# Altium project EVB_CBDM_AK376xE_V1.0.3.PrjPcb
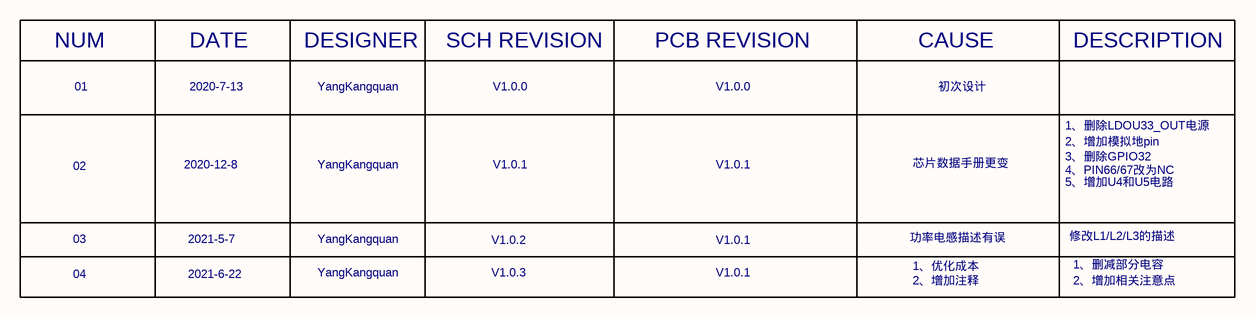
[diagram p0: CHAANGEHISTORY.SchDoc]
7 sheets, 156 parts. Net scope: flat (ports and power ports of the same name join across sheets).
Sheets:
  CHAANGEHISTORY.SchDoc
  BLOCK_DIAGRAM.SchDoc
  INTERFACE_CORE.SchDoc
  AK376xE_POWER.SchDoc
  AK376xE_FLASH.SchDoc
  AK376xE_MIC.SchDoc
  POWER.SchDoc

## Sheet CHAANGEHISTORY.SchDoc: EVB_CBDM_AK376xE_V1.0.3
size A4; Revision: V1.0.3; SheetNumber: 1; SheetTotal: 7

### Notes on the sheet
- NUM
- 01
- DATE
- 2020-7-13
- DESIGNER
- YangKangquan
- SCH REVISION
- V1.0.0
- PCB REVISION
- CAUSE
- 初次设计
- DESCRIPTION
- 02
- 2020-12-8
- V1.0.1
- 芯片数据手册更变
- 1、删除LDOU33_OUT电源
- 2、增加模拟地pin
- 3、删除GPIO32
- 4、PIN66/67改为NC
- 03
- 2021-5-7
- V1.0.2
- 功率电感描述有误
- 5、增加U4和U5电路
- 修改L1/L2/L3的描述
- 04
- 2021-6-22
- V1.0.3
- 1、优化成本
- 2、增加注释
- 1、删减部分电容
- 2、增加相关注意点

## Sheet BLOCK_DIAGRAM.SchDoc: EVB_CBDM_AK376xE_V1.0.3
size A4; Revision: V1.0.3; SheetNumber: 2; SheetTotal: 7
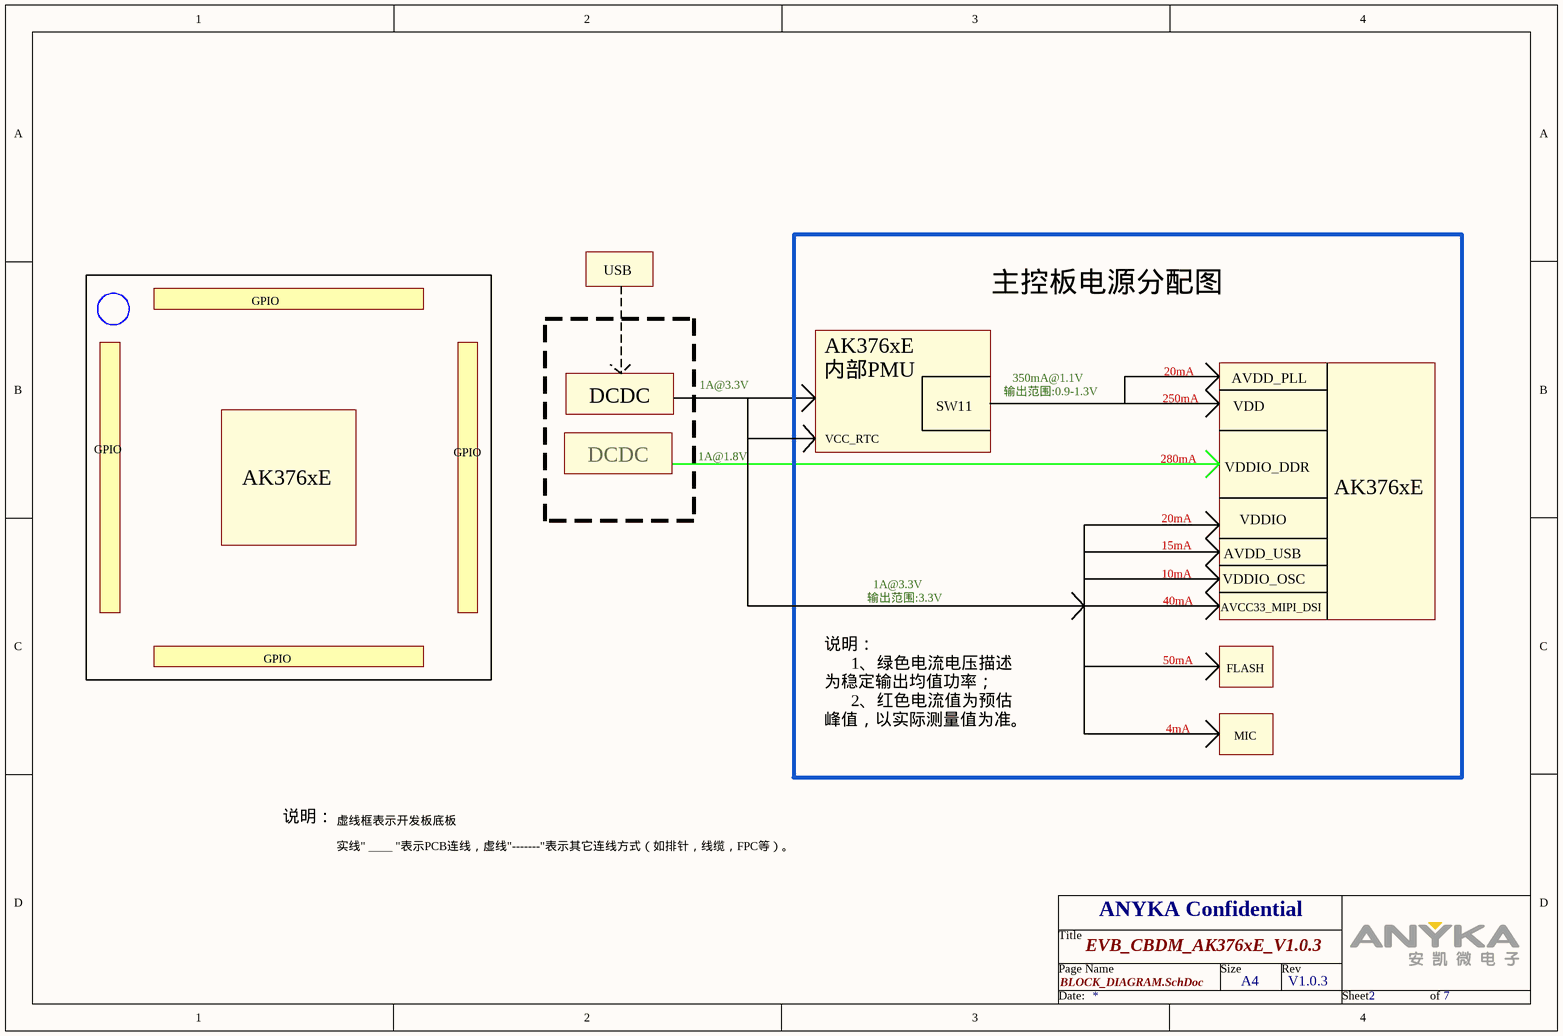
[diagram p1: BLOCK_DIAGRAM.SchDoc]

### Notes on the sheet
- GPIO
- USB
- 主控板电源分配图
- AK376xE
  内部PMU
- 20mA
- AVDD_PLL
- DCDC
- 1A@3.3V
- VCC_RTC
- 350mA@1.1V
  输出范围:0.9-1.3V
- 250mA
- VDD
- AK376xE
- 1A@1.8V
- SW11
- 280mA
- VDDIO_DDR
- 10mA
- 15mA
- AVDD_USB
- VDDIO_OSC
- VDDIO
- 1A@3.3V
  输出范围:3.3V
- 40mA
- AVCC33_MIPI_DSI
- 50mA
- FLASH
- 说明：
  1、绿色电流电压描述为稳定输出均值功率；
  2、红色电流值为预估峰值，以实际测量值为准。
- 4mA
- MIC
- 说明：
- 虚线框表示开发板底板
- 实线" ____ "表示PCB连线，虚线"-------"表示其它连线方式（如排针，线缆，FPC等）。

## Sheet INTERFACE_CORE.SchDoc: EVB_CBDM_AK376xE_V1.0.3
size A4; Revision: V1.0.3; SheetNumber: 3; SheetTotal: 7
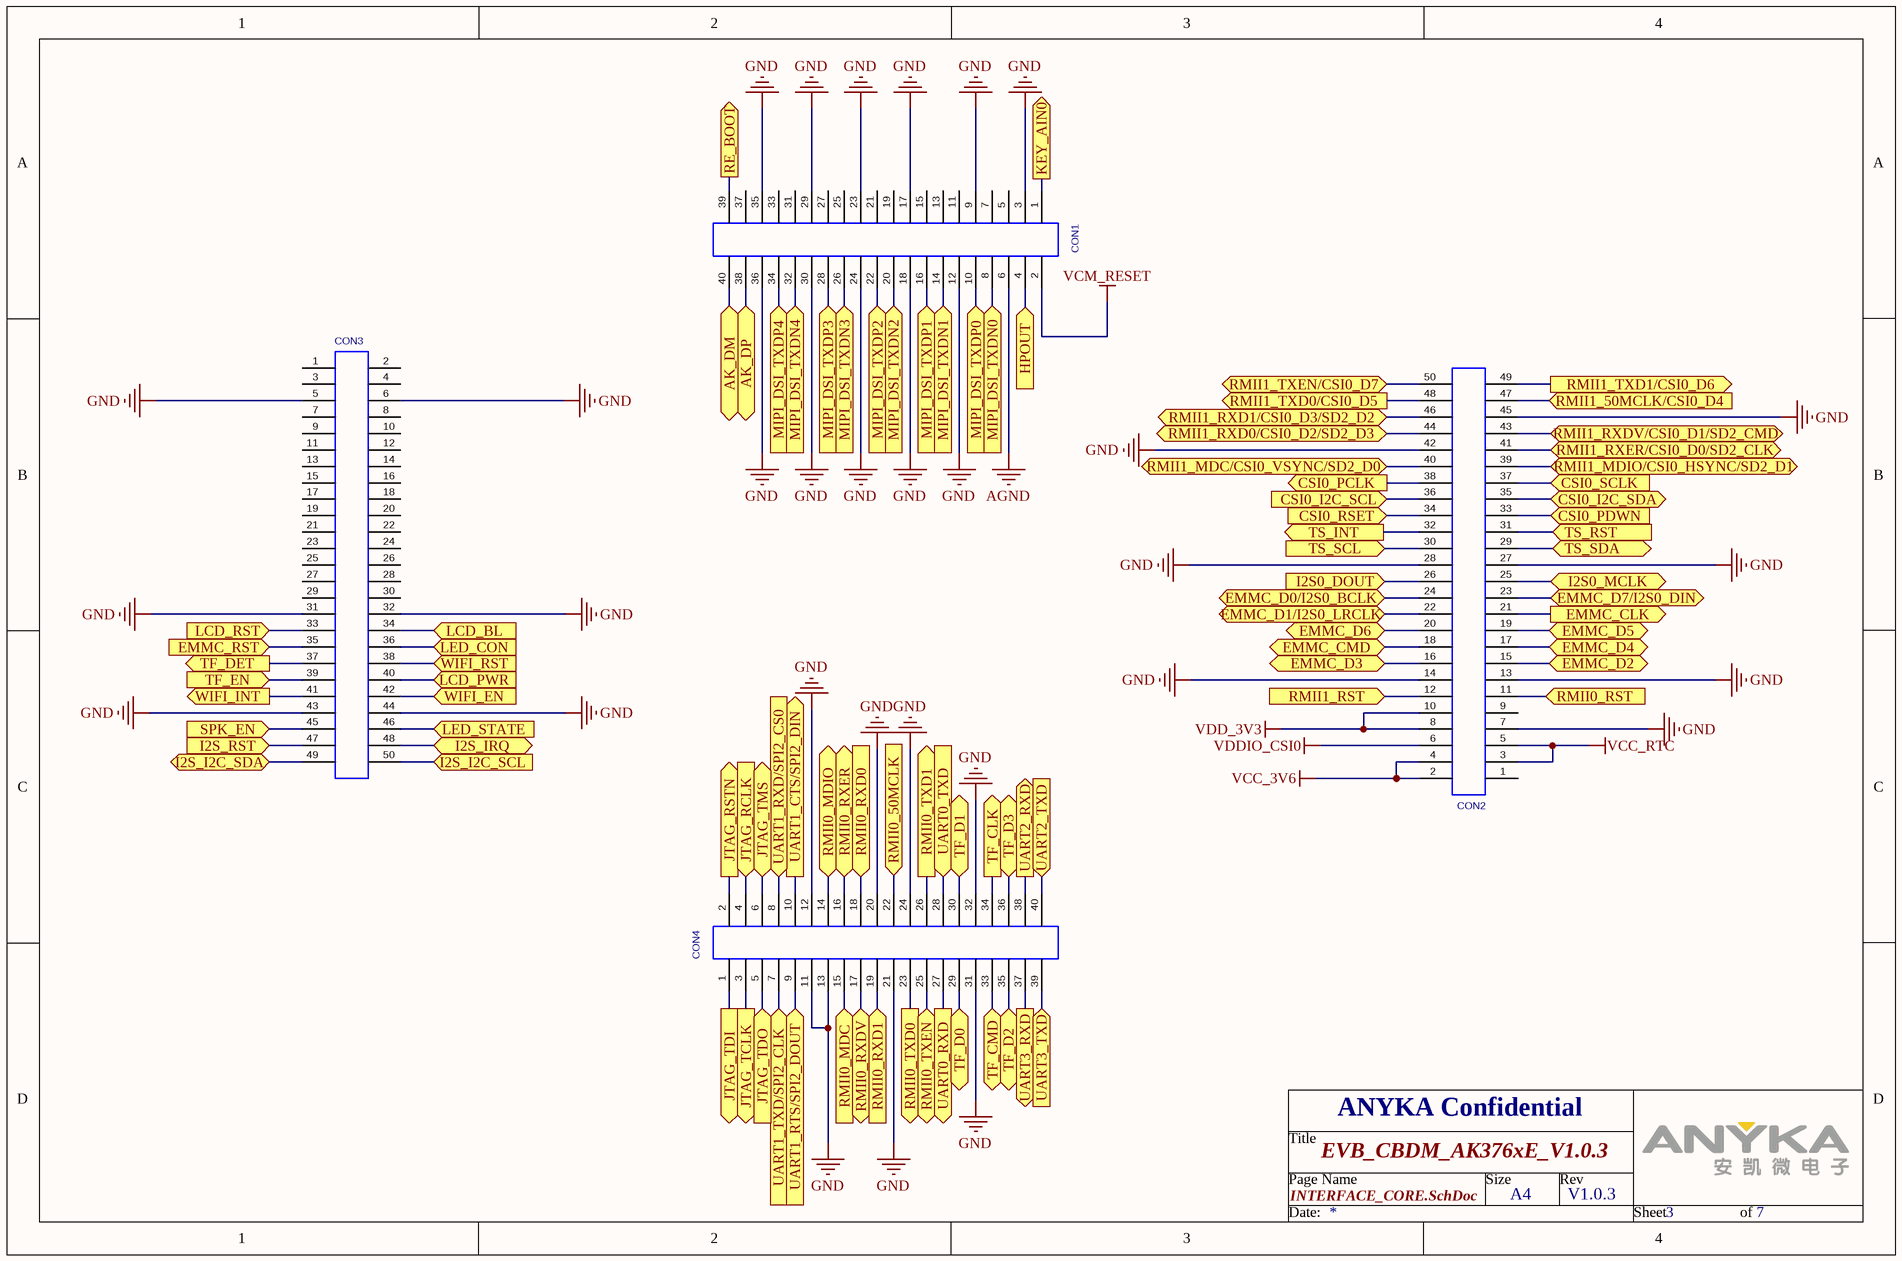
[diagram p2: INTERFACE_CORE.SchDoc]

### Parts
CON1  CON20X2_0MM5_BTB_DF12  [CON20X2_0MM5_BTB_DF12_N]  (value not drawn)
CON2  CON25X2_0MM5_BTB_DF12  [CON25X2_0MM5_BTB_DF12_N]  (value not drawn)
CON3  CON25X2_0MM5_BTB_DF12  [CON25X2_0MM5_BTB_DF12_N]  (value not drawn)
CON4  CON20X2_0MM5_BTB_DF12  [CON20X2_0MM5_BTB_DF12_N]  (value not drawn)

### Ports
AK_DM (bidir), AK_DP (bidir), CSI0_I2C_SCL (in), CSI0_I2C_SDA (bidir), CSI0_PCLK (out), CSI0_PDWN (in), CSI0_RSET (in), CSI0_SCLK (in), EMMC_CLK (out), EMMC_CMD (bidir), EMMC_D0/I2S0_BCLK (bidir), EMMC_D1/I2S0_LRCLK (bidir), EMMC_D2 (bidir), EMMC_D3 (bidir), EMMC_D4 (bidir), EMMC_D5 (bidir), EMMC_D6 (bidir), EMMC_D7/I2S0_DIN (bidir), EMMC_RST (in), HPOUT (in), I2S0_DOUT (in), I2S0_MCLK (bidir), I2S_I2C_SCL (in), I2S_I2C_SDA (bidir), I2S_IRQ (bidir), I2S_RST (in), JTAG_RCLK (in), JTAG_RSTN (out), JTAG_TCLK (out), JTAG_TDI (out), JTAG_TDO (in), JTAG_TMS (bidir), KEY_AIN0 (out), LCD_BL (in), LCD_PWR (in), LCD_RST (in), LED_CON (in), LED_STATE (in), MIPI_DSI_TXDN0 (in), MIPI_DSI_TXDN1 (in), MIPI_DSI_TXDN2 (in), MIPI_DSI_TXDN3 (in), MIPI_DSI_TXDN4 (in), MIPI_DSI_TXDP0 (in), MIPI_DSI_TXDP1 (in), MIPI_DSI_TXDP2 (in), MIPI_DSI_TXDP3 (in), MIPI_DSI_TXDP4 (in), RE_BOOT (out), RMII0_50MCLK (in), RMII0_MDC (in), RMII0_MDIO (bidir), RMII0_RST (in), RMII0_RXD0 (in), RMII0_RXD1 (in), RMII0_RXDV (bidir), RMII0_RXER (bidir), RMII0_TXD0 (out), RMII0_TXD1 (out), RMII0_TXEN (bidir), RMII1_50MCLK/CSI0_D4 (in), RMII1_MDC/CSI0_VSYNC/SD2_D0 (bidir), RMII1_MDIO/CSI0_HSYNC/SD2_D1 (bidir), RMII1_RST (in), RMII1_RXD0/CSI0_D2/SD2_D3 (bidir), RMII1_RXD1/CSI0_D3/SD2_D2 (bidir), RMII1_RXDV/CSI0_D1/SD2_CMD (bidir), RMII1_RXER/CSI0_D0/SD2_CLK (bidir), RMII1_TXD0/CSI0_D5 (out), RMII1_TXD1/CSI0_D6 (out), RMII1_TXEN/CSI0_D7 (bidir), SPK_EN (in), TF_CLK (out), TF_CMD (bidir), TF_D0 (bidir), TF_D1 (bidir), TF_D2 (bidir), TF_D3 (bidir), TF_DET (out), TF_EN (in), TS_INT (out), TS_RST (in), TS_SCL (in), TS_SDA (bidir), UART0_RXD (out), UART0_TXD (in), UART1_CTS/SPI2_DIN (out), UART1_RTS/SPI2_DOUT (in), UART1_RXD/SPI2_CS0 (in), UART1_TXD/SPI2_CLK (in), UART2_RXD (out), UART2_TXD (in), UART3_RXD (out), UART3_TXD (in), WIFI_EN (in), WIFI_INT (out), WIFI_RST (in)

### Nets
AGND: CON1.6
GND: CON1.3 CON1.9 CON1.12 CON1.17 CON1.18 CON1.23 CON1.24 CON1.29 CON1.30 CON1.35 CON1.36 CON2.7 CON2.13 CON2.14 CON2.27 CON2.28 CON2.42 CON2.45 CON3.5 CON3.6 CON3.31 CON3.32 CON3.43 CON3.44 CON4.11 CON4.12 CON4.13 CON4.20 CON4.21 CON4.24 CON4.31 CON4.32
VCC_3V6: CON2.2 CON2.4
VCC_RTC: CON2.3 CON2.5
VCM_RESET: CON1.2
VDD_3V3: CON2.8 CON2.10
VDDIO_CSI0: CON2.6
AK_DM: CON1.40 ; port AK_DM
AK_DP: CON1.38 ; port AK_DP
CSI0_I2C_SCL: CON2.36 ; port CSI0_I2C_SCL
CSI0_I2C_SDA: CON2.35 ; port CSI0_I2C_SDA
CSI0_PCLK: CON2.38 ; port CSI0_PCLK
CSI0_PDWN: CON2.33 ; port CSI0_PDWN
CSI0_RSET: CON2.34 ; port CSI0_RSET
CSI0_SCLK: CON2.37 ; port CSI0_SCLK
EMMC_CLK: CON2.21 ; port EMMC_CLK
EMMC_CMD: CON2.18 ; port EMMC_CMD
EMMC_D0/I2S0_BCLK: CON2.24 ; port EMMC_D0/I2S0_BCLK
EMMC_D1/I2S0_LRCLK: CON2.22 ; port EMMC_D1/I2S0_LRCLK
EMMC_D2: CON2.15 ; port EMMC_D2
EMMC_D3: CON2.16 ; port EMMC_D3
EMMC_D4: CON2.17 ; port EMMC_D4
EMMC_D5: CON2.19 ; port EMMC_D5
EMMC_D6: CON2.20 ; port EMMC_D6
EMMC_D7/I2S0_DIN: CON2.23 ; port EMMC_D7/I2S0_DIN
HPOUT: CON1.4 ; port HPOUT
I2S0_DOUT: CON2.26 ; port I2S0_DOUT
I2S0_MCLK: CON2.25 ; port I2S0_MCLK
I2S_I2C_SCL: CON3.50 ; port I2S_I2C_SCL
I2S_I2C_SDA: CON3.49 ; port I2S_I2C_SDA
I2S_RST: CON3.47 ; port I2S_RST
JTAG_RCLK: CON4.4 ; port JTAG_RCLK
JTAG_RSTN: CON4.2 ; port JTAG_RSTN
JTAG_TCLK: CON4.3 ; port JTAG_TCLK
JTAG_TDI: CON4.1 ; port JTAG_TDI
JTAG_TDO: CON4.5 ; port JTAG_TDO
JTAG_TMS: CON4.6 ; port JTAG_TMS
KEY_AIN0: CON1.1 ; port KEY_AIN0
LCD_BL: CON3.34 ; port LCD_BL
LCD_PWR: CON3.40 ; port LCD_PWR
LCD_RST: CON3.33 ; port LCD_RST
LED_CON: CON3.36 ; port LED_CON
LED_STATE: CON3.46 ; port LED_STATE
MIPI_DSI_TXDN0: CON1.8 ; port MIPI_DSI_TXDN0
MIPI_DSI_TXDN1: CON1.14 ; port MIPI_DSI_TXDN1
MIPI_DSI_TXDN2: CON1.20 ; port MIPI_DSI_TXDN2
MIPI_DSI_TXDN3: CON1.26 ; port MIPI_DSI_TXDN3
MIPI_DSI_TXDN4: CON1.32 ; port MIPI_DSI_TXDN4
MIPI_DSI_TXDP0: CON1.10 ; port MIPI_DSI_TXDP0
MIPI_DSI_TXDP1: CON1.16 ; port MIPI_DSI_TXDP1
MIPI_DSI_TXDP2: CON1.22 ; port MIPI_DSI_TXDP2
MIPI_DSI_TXDP3: CON1.28 ; port MIPI_DSI_TXDP3
MIPI_DSI_TXDP4: CON1.34 ; port MIPI_DSI_TXDP4
RMII0_50MCLK: CON4.22 ; port RMII0_50MCLK
RMII0_MDC: CON4.15 ; port RMII0_MDC
RMII0_MDIO: CON4.14 ; port RMII0_MDIO
RMII0_RST: CON2.11 ; port RMII0_RST
RMII0_RXD0: CON4.18 ; port RMII0_RXD0
RMII0_RXD1: CON4.19 ; port RMII0_RXD1
RMII0_RXDV: CON4.17 ; port RMII0_RXDV
RMII0_RXER: CON4.16 ; port RMII0_RXER
RMII0_TXD0: CON4.23 ; port RMII0_TXD0
RMII0_TXD1: CON4.26 ; port RMII0_TXD1
RMII0_TXEN: CON4.25 ; port RMII0_TXEN
RMII1_MDC/CSI0_VSYNC/SD2_D0: CON2.40 ; port RMII1_MDC/CSI0_VSYNC/SD2_D0
RMII1_MDIO/CSI0_HSYNC/SD2_D1: CON2.39 ; port RMII1_MDIO/CSI0_HSYNC/SD2_D1
RMII1_RST: CON2.12 ; port RMII1_RST
RMII1_RXD0/CSI0_D2/SD2_D3: CON2.44 ; port RMII1_RXD0/CSI0_D2/SD2_D3
RMII1_RXD1/CSI0_D3/SD2_D2: CON2.46 ; port RMII1_RXD1/CSI0_D3/SD2_D2
RMII1_RXDV/CSI0_D1/SD2_CMD: CON2.43 ; port RMII1_RXDV/CSI0_D1/SD2_CMD
RMII1_RXER/CSI0_D0/SD2_CLK: CON2.41 ; port RMII1_RXER/CSI0_D0/SD2_CLK
RMII1_TXD0/CSI0_D5: CON2.48 ; port RMII1_TXD0/CSI0_D5
RMII1_TXD1/CSI0_D6: CON2.49 ; port RMII1_TXD1/CSI0_D6
RMII1_TXEN/CSI0_D7: CON2.50 ; port RMII1_TXEN/CSI0_D7
SPK_EN: CON3.45 ; port SPK_EN
TF_CLK: CON4.34 ; port TF_CLK
TF_CMD: CON4.33 ; port TF_CMD
TF_D0: CON4.29 ; port TF_D0
TF_D1: CON4.30 ; port TF_D1
TF_D2: CON4.35 ; port TF_D2
TF_D3: CON4.36 ; port TF_D3
TF_DET: CON3.37 ; port TF_DET
TF_EN: CON3.39 ; port TF_EN
TS_INT: CON2.32 ; port TS_INT
TS_RST: CON2.31 ; port TS_RST
TS_SCL: CON2.30 ; port TS_SCL
TS_SDA: CON2.29 ; port TS_SDA
UART0_RXD: CON4.27 ; port UART0_RXD
UART0_TXD: CON4.28 ; port UART0_TXD
UART1_CTS/SPI2_DIN: CON4.10 ; port UART1_CTS/SPI2_DIN
UART1_RTS/SPI2_DOUT: CON4.9 ; port UART1_RTS/SPI2_DOUT
UART1_RXD/SPI2_CS0: CON4.8 ; port UART1_RXD/SPI2_CS0
UART1_TXD/SPI2_CLK: CON4.7 ; port UART1_TXD/SPI2_CLK
UART2_RXD: CON4.38 ; port UART2_RXD
UART2_TXD: CON4.40 ; port UART2_TXD
UART3_RXD: CON4.37 ; port UART3_RXD
UART3_TXD: CON4.39 ; port UART3_TXD
WIFI_EN: CON3.42 ; port WIFI_EN
WIFI_INT: CON3.41 ; port WIFI_INT
WIFI_RST: CON3.38 ; port WIFI_RST
NetCON1_39: CON1.39 ; port RE_BOOT
NetCON2_47: CON2.47 ; port RMII1_50MCLK/CSI0_D4
NetCON3_35: CON3.35 ; port EMMC_RST
NetCON3_48: CON3.48 ; port I2S_IRQ

Not connected (* = marked no-connect by the designer): CON1 5 7 11 13 15 19 21 25 27 31 33 37; CON2 1 9; CON3 1 2 3 4 7 8 9 10 11 12 13 14 15 16 17 18 19 20 21 22 23 24 25 26 27 28 29 30

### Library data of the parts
CON1 CON4 = CNBBM4000XX: 0.5mm ，BTB2*20Pin，SMT，公座，H3.0，DF12#(3.0)-40DS-0.5; PCB DECAL: CON20X2_0MM5_BTB_DF12_BOTTOM; Catalog: Connector
CON2 CON3 = CNBBM5000XX: 0.5mm ，BTB2*25Pin，SMT，公座，H3.0，DF12#(3.0)-50DS-0.5; Catalog: Connector

## Sheet AK376xE_POWER.SchDoc: EVB_CBDM_AK376xE_V1.0.3
size A4; Revision: V1.0.3; SheetNumber: 4; SheetTotal: 7
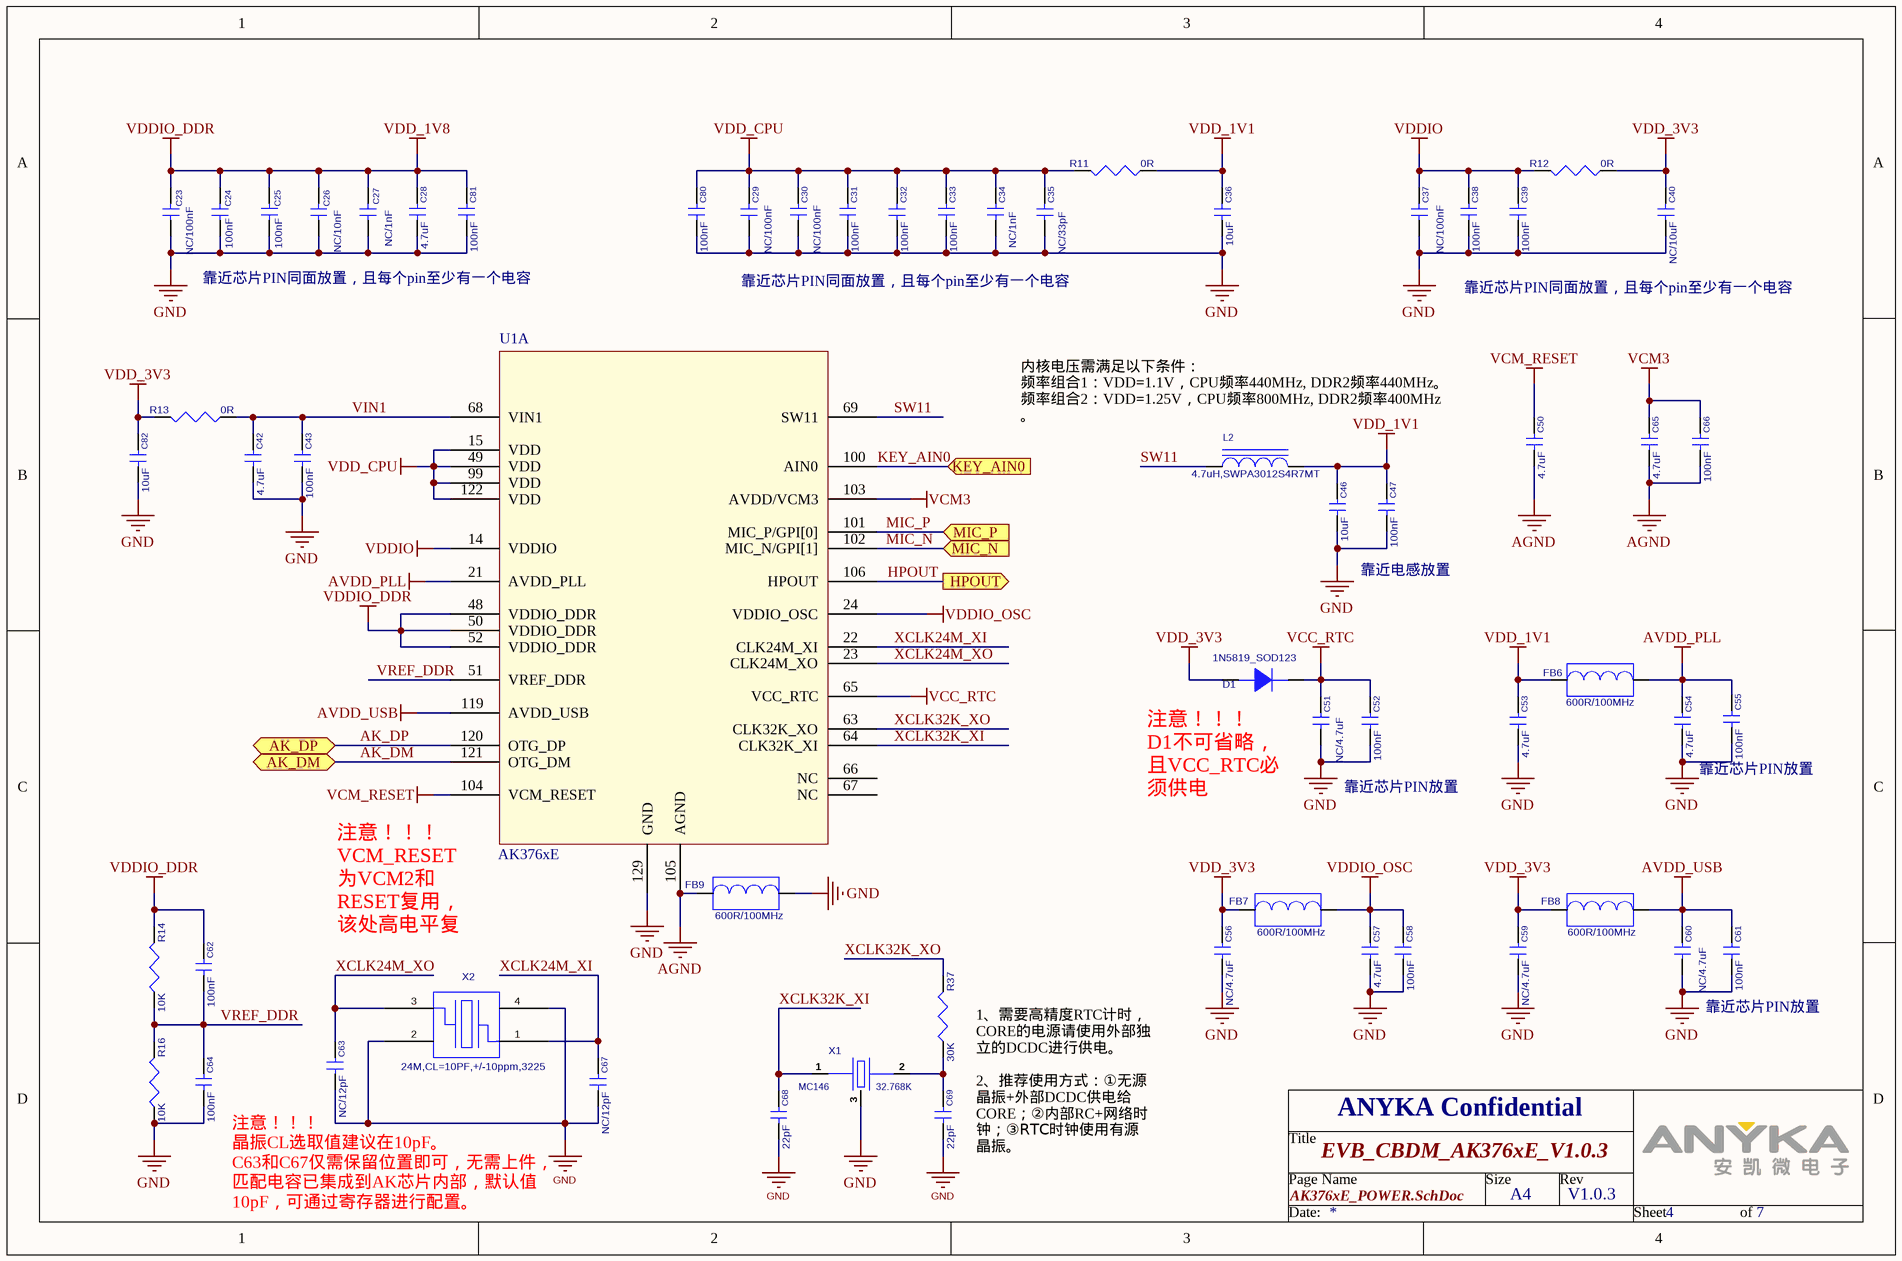
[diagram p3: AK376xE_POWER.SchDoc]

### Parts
C23  NC/100nF  [C0603]
C24  100nF  [C0603]
C25  100nF  [C0402]
C26  NC/10nF  [C0603]
C27  NC/1nF  [C0603]
C28  4.7uF  [C0402]
C29  NC/100nF  [C0603]
C30  NC/100nF  [C0402]
C31  100nF  [C0402]
C32  100nF  [C0603]
C33  100nF  [C0402]
C34  NC/1nF  [C0402]
C35  NC/33pF  [C0603]
C36  10uF  [C0603]
C37  NC/100nF  [C0603]
C38  100nF  [C0402]
C39  100nF  [C0402]
C40  NC/10uF  [C0603]
C42  4.7uF  [C0603]
C43  100nF  [C0603]
C46  10uF  [C0603]
C47  100nF  [C0603]
C50  4.7uF  [C0603]
C51  NC/4.7uF  [C0603]
C52  100nF  [C0603]
C53  4.7uF  [C0603]
C54  4.7uF  [C0402]
C55  100nF  [C0402]
C56  NC/4.7uF  [C0603]
C57  4.7uF  [C0402]
C58  100nF  [C0402]
C59  NC/4.7uF  [C0603]
C60  NC/4.7uF  [C0603]
C61  100nF  [C0402]
C62  100nF  [C0603]
C63  NC/12pF  [C0402]
C64  100nF  [C0603]
C65  4.7uF  [C0603]
C66  100nF  [C0603]
C67  NC/12pF  [C0402]
C68  22pF  [C0603]
C69  22pF  [C0603]
C80  100nF  [C0402]
C81  100nF  [C0402]
C82  10uF  [C0603]
D1  1N5819_SOD123  [1N5819_SOD123]  (value not drawn)
FB6  600R/100MHz  [FB0603]
FB7  600R/100MHz  [FB0603]
FB8  600R/100MHz  [FB0603]
FB9  600R/100MHz  [FB0603]
L2  4.7uH,SWPA3012S4R7MT  [L_SWPA3012_3X3MM]
R11  0R  [R0805]
R12  0R  [R0805]
R13  0R  [R0805]
R14  10K  [R0603]
R16  10K  [R0603]
R37  30K  [R0603]
U1  AK376xE  [LQFP128_0MM4_16X16MM]  (part A of 3)
X1  32.768K  [MC146]
X2  24M,CL=10PF,+/-10ppm,3225  [3225]

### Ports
AK_DM (bidir), AK_DP (bidir), HPOUT (out), KEY_AIN0 (in), MIC_N (in), MIC_P (in)

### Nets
AGND: C50.2 C65.2 C66.2 FB9.1 U1.105(AGND)
AVDD_PLL: C54.1 C55.1 FB6.2 U1.21(AVDD_PLL)
AVDD_USB: C60.1 C61.1 FB8.2 U1.119(AVDD_USB)
GND: C23.1 C24.1 C25.2 C26.1 C27.1 C28.2 C29.1 C30.2 C31.2 C32.1 C33.2 C34.2 C35.1 C36.1 C37.1 C38.2 C39.2 C40.1 C42.2 C43.2 C46.2 C47.2 C51.2 C52.2 C53.2 C54.2 C55.2 C56.2 C57.2 C58.2 C59.2 C60.2 C61.2 C63.2 C64.2 C67.2 C68.2 C69.2 C80.2 C81.2 C82.2 FB9.2 R16.1 U1.129(GND) X1.3(GND) X2.2 X2.4
VCC_RTC: C51.1 C52.1 D1.K U1.65(VCC_RTC)
VCM3: C65.1 C66.1 U1.103(AVDD/VCM3)
VCM_RESET: C50.1 U1.104(VCM_RESET)
VDD_1V1: C36.2 C46.1 C47.1 C53.1 FB6.1 L2.2 R11.1
VDD_1V8: C23.2 C24.2 C25.1 C26.2 C27.2 C28.1 C62.1 C81.1 R14.2 U1.48(VDDIO_DDR) U1.50(VDDIO_DDR) U1.52(VDDIO_DDR)  [also labelled VDDIO_DDR]
VDD_3V3: C40.2 C56.1 C59.1 C82.1 D1.A FB7.1 FB8.1 R12.1 R13.2
VDD_CPU: C29.2 C30.1 C31.1 C32.2 C33.1 C34.1 C35.2 C80.1 R11.2 U1.15(VDD) U1.49(VDD) U1.99(VDD) U1.122(VDD)
VDDIO: C37.2 C38.1 C39.1 R12.2 U1.14(VDDIO)
VDDIO_OSC: C57.1 C58.1 FB7.2 U1.24(VDDIO_OSC)
AK_DM: U1.121(OTG_DM) ; port AK_DM
AK_DP: U1.120(OTG_DP) ; port AK_DP
HPOUT: U1.106(HPOUT) ; port HPOUT
KEY_AIN0: U1.100(AIN0) ; port KEY_AIN0
MIC_N: U1.102(MIC_N/GPI[1]) ; port MIC_N
MIC_P: U1.101(MIC_P/GPI[0]) ; port MIC_P
SW11: L2.1 U1.69(SW11)
VIN1: C42.1 C43.1 R13.1 U1.68(VIN1)
VREF_DDR: C62.2 C64.1 R14.1 R16.2 U1.51(VREF_DDR)
XCLK24M_XI: C67.1 U1.22(CLK24M_XI) X2.1
XCLK24M_XO: C63.1 U1.23(CLK24M_XO) X2.3
XCLK32K_XI: C68.1 U1.64(CLK32K_XI) X1.1
XCLK32K_XO: R37.2 U1.63(CLK32K_XO)
NetC69_1: C69.1 R37.1 X1.2(GND1)

Not connected (* = marked no-connect by the designer): U1 66(NC) 67(NC)

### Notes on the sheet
- 靠近芯片PIN同面放置，且每个pin至少有一个电容
- (near L2) 内核电压需满足以下条件：
  频率组合1：VDD=1.1V，CPU频率440MHz, DDR2频率440MHz。
  频率组合2：VDD=1.25V，CPU频率800MHz, DDR2频率400MHz。
- 靠近电感放置
- 靠近芯片PIN放置
- 注意！！！
  D1不可省略，且VCC_RTC必须供电
- (near U1) 注意！！！
  VCM_RESET为VCM2和RESET复用，该处高电平复位
- 1、需要高精度RTC计时，CORE的电源请使用外部独立的DCDC进行供电。
  2、推荐使用方式：①无源晶振+外部DCDC供电给CORE；②内部RC+网络时钟；③RTC时钟使用有源晶振。
- 注意！！！
  晶振CL选取值建议在10pF。
  C63和C67仅需保留位置即可，无需上件，匹配电容已集成到AK芯片内部，默认值10pF，可通过寄存器进行配置。

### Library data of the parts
C23 C29 C37 = CC0301040XX: C/C,100nF,25V,+/-5%,0603; Remark: NC; Catalog: 陶瓷电容
C24 C32 C43 C47 C52 C62 C64 C66 = CC0301040XX: C/C,100nF,25V,+/-5%,0603; Catalog: 陶瓷电容
C25 C31 C33 C38 C39 C55 C58 C61 C80 C81 = CC0201040XX: C/C,100nF,25V,+/-5%,0402; Catalog: 陶瓷电容
C26 = CC0301032XX: C/C,10nF,50V,+/-10%,0603; Remark: NC; Catalog: 陶瓷电容
C27 = CC0301020XX: C/C,1nF,25V,+/-5%,0603; Remark: NC; Catalog: 陶瓷电容
C28 C54 C57 = CC0204751XX: C/C,4.7uF,10V,+/-10%,0402; Catalog: 陶瓷电容
C30 = CC0201040XX: C/C,100nF,25V,+/-5%,0402; Remark: NC; Catalog: 陶瓷电容
C34 = CC0201020XX: C/C,1nF,25V,+/-5%,0402; Remark: NC; Catalog: 陶瓷电容
C35 = CC0303300XX: C/C,33pF,25V,+/-5%,0603; Remark: NC; Catalog: 陶瓷电容
C36 C46 C82 = CC0301061XX: C/C,10uF,25V,+/-20%,0603; Catalog: 陶瓷电容
C40 = CC0301061XX: C/C,10uF,25V,+/-20%,0603; Remark: NC; Catalog: 陶瓷电容
C42 C50 C53 C65 = CC0304751XX: C/C,4.7uF,16V,+/-10%,0603; Catalog: 陶瓷电容
C51 C56 C59 C60 = CC0304751XX: C/C,4.7uF,16V,+/-10%,0603; Remark: NC; Catalog: 陶瓷电容
C63 C67 = CC02012R0XX: C/C,12pF,25V,+/-5%,0402; Remark: NC; Catalog: 陶瓷电容
C68 C69 = CC0302200XX: C/C,22pF,25V,+/-5%,0603; Catalog: 陶瓷电容
D1 = DD32SCH04XX: 1N5819_SOD123_1MM7X3MM85; Part Number_AK: DD06SCH00XX; Source_Path: E:\PROJECTS\JVS-H201\LIBRARY1.OLB; CODE: 82268; Catalog: 二极管
FB6-FB9 = BE0306011XX: BLM18BD601SN1, 600R@100MHz; SOURCE_PATH: D:\PROGRAM FILES\ORCAD\ORCAD_10.5\TOOLS\CAPTURE\LIBRARY\DISCRETE.OLB; Catalog: 贴片磁珠
L2 = WL1C04R70XX: Part Number_AK: WL1C02R20XX; SOURCE_PATH: E:\工作目录\ORCAD原理图库\ORCAD元件库\磁珠&电感.OLB; Catalog: 贴片电感
R11-R13 = CR0500000XX: Res,0R,1/8W,+/-5%,0805; Catalog: 贴片电阻
R14 R16 = CR0310020XX: Res,10K,1/10W,+/-1%,0603; Catalog: 贴片电阻
R37 = CR0303030XX: Res,30K,1/10W,+/-5%,0603; Catalog: 贴片电阻
U1 = 11111111110: AK376xE_LQFP128_0MM4_16X16MM; Catalog: AK芯片
X1 = XR32K77S2XX: 32.768K,CL=12.5pF,20ppm,MC146; Catalog: 晶振
X2 = XR24M00S4XX: Catalog: 晶振

## Sheet AK376xE_FLASH.SchDoc: EVB_CBDM_AK376xE_V1.0.3
size A4; Revision: V1.0.3; SheetNumber: 5; SheetTotal: 7
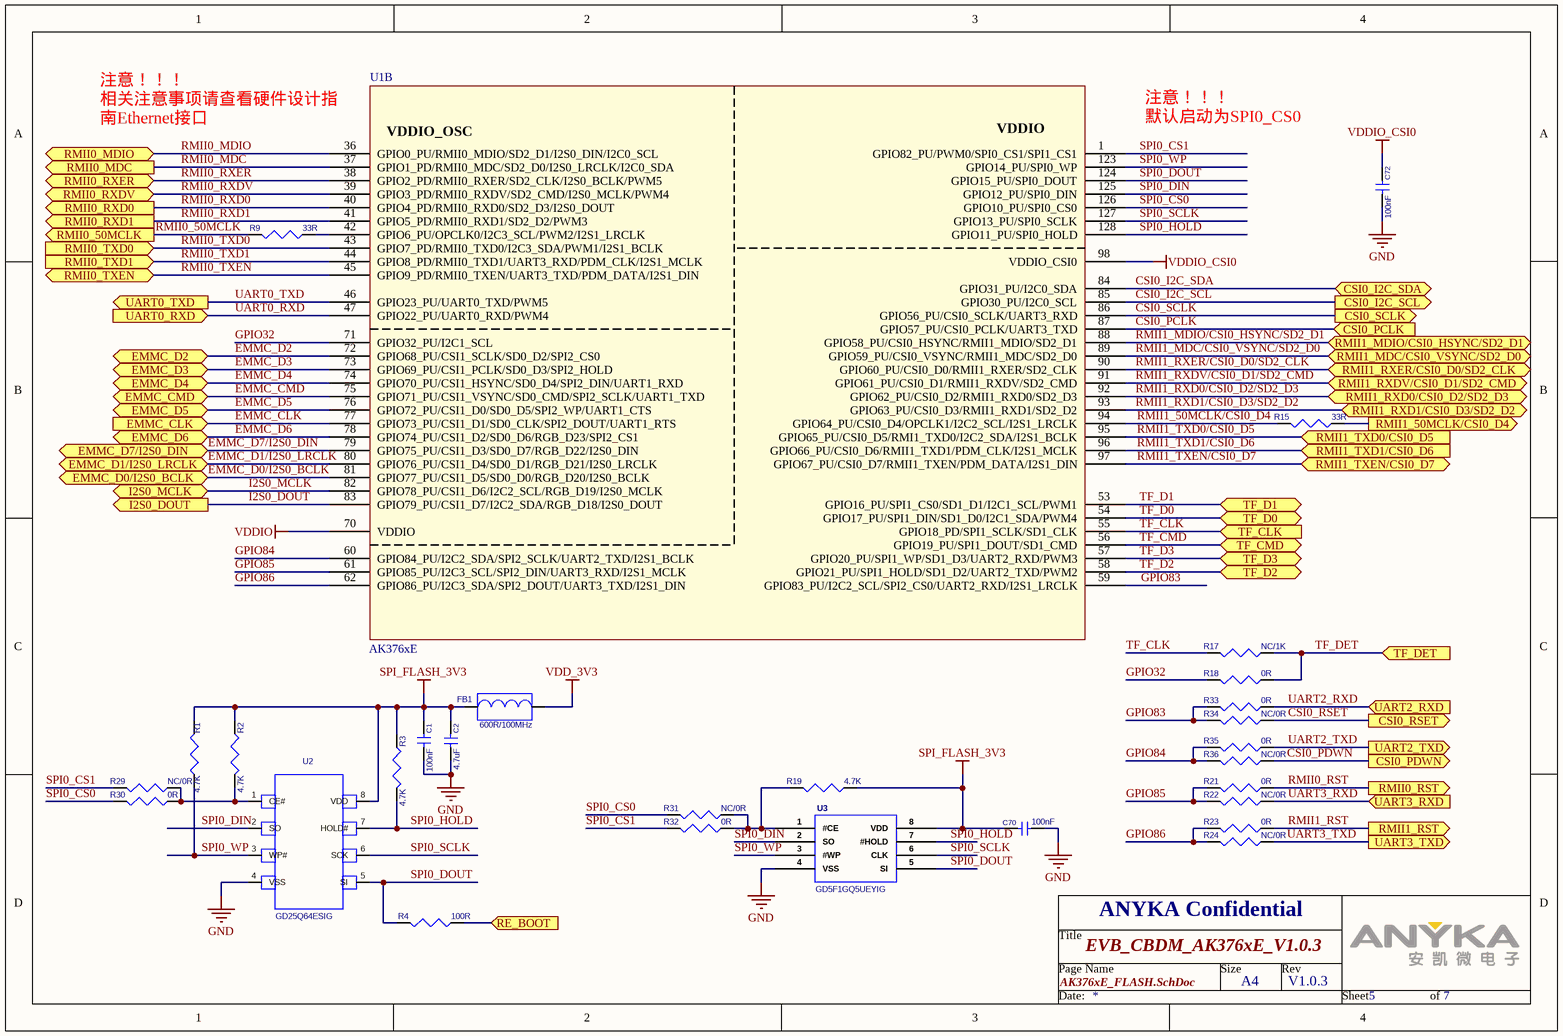
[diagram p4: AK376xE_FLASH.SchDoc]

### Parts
C1  100nF  [C0603]
C2  4.7uF  [C0603]
C70  100nF  [C0603]
C72  100nF  [C0402]
FB1  600R/100MHz  [FB0603]
R1  4.7K  [R0603]
R2  4.7K  [R0603]
R3  4.7K  [R0603]
R4  100R  [R0603]
R9  33R  [R0603]
R15  33R  [R0603]
R17  NC/1K  [R0603]
R18  0R  [R0603]
R19  4.7K  [R0603]
R21  0R  [R0603]
R22  NC/0R  [R0603]
R23  0R  [R0603]
R24  NC/0R  [R0603]
R29  NC/0R  [R0603]
R30  0R  [R0603]
R31  NC/0R  [R0603]
R32  0R  [R0603]
R33  0R  [R0603]
R34  NC/0R  [R0603]
R35  0R  [R0603]
R36  NC/0R  [R0603]
U1  AK376xE  [LQFP128_0MM4_16X16MM]  (part B of 3)
U2  GD25Q64ESIG  [GD25Q64ESIG_SOP8_1MM27_5X8MM]
U3  GD5F1GQ5UEYIG  [GD5F1GQ5UEYIG_SOP8_1MM27_6X8MM]

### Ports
CSI0_I2C_SCL (out), CSI0_I2C_SDA (bidir), CSI0_PCLK (in), CSI0_PDWN (out), CSI0_RSET (out), CSI0_SCLK (out), EMMC_CLK (in), EMMC_CMD (bidir), EMMC_D0/I2S0_BCLK (bidir), EMMC_D1/I2S0_LRCLK (bidir), EMMC_D2 (bidir), EMMC_D3 (bidir), EMMC_D4 (bidir), EMMC_D5 (bidir), EMMC_D6 (bidir), EMMC_D7/I2S0_DIN (bidir), I2S0_DOUT (out), I2S0_MCLK (bidir), RE_BOOT (in), RMII0_50MCLK (out), RMII0_MDC (out), RMII0_MDIO (bidir), RMII0_RST (out), RMII0_RXD0 (out), RMII0_RXD1 (out), RMII0_RXDV (bidir), RMII0_RXER (bidir), RMII0_TXD0 (in), RMII0_TXD1 (in), RMII0_TXEN (bidir), RMII1_50MCLK/CSI0_D4 (out), RMII1_MDC/CSI0_VSYNC/SD2_D0 (bidir), RMII1_MDIO/CSI0_HSYNC/SD2_D1 (bidir), RMII1_RST (out), RMII1_RXD0/CSI0_D2/SD2_D3 (bidir), RMII1_RXD1/CSI0_D3/SD2_D2 (bidir), RMII1_RXDV/CSI0_D1/SD2_CMD (bidir), RMII1_RXER/CSI0_D0/SD2_CLK (bidir), RMII1_TXD0/CSI0_D5 (in), RMII1_TXD1/CSI0_D6 (in), RMII1_TXEN/CSI0_D7 (bidir), TF_CLK (in), TF_CMD (bidir), TF_D0 (bidir), TF_D1 (bidir), TF_D2 (bidir), TF_D3 (bidir), TF_DET (in), UART0_RXD (in), UART0_TXD (out), UART2_RXD (in), UART2_TXD (out), UART3_RXD (in), UART3_TXD (out)

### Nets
GND: C1.2 C2.1 C70.2 C72.2 U2.4(VSS) U3.4(VSS)
SPI_FLASH_3V3: C1.1 C2.2 C70.1 FB1.1 R1.1 R2.1 R3.1 R19.1 U2.8(VDD) U3.8(VDD)
VDD_3V3: FB1.2
VDDIO: U1.70(VDDIO)
VDDIO_CSI0: C72.1 U1.98(VDDIO_CSI0)
CSI0_I2C_SCL: U1.85(GPIO30_PU/I2C0_SCL) ; port CSI0_I2C_SCL
CSI0_I2C_SDA: U1.84(GPIO31_PU/I2C0_SDA) ; port CSI0_I2C_SDA
CSI0_PCLK: U1.87(GPIO57_PU/CSI0_PCLK/UART3_TXD) ; port CSI0_PCLK
CSI0_PDWN: R36.1 ; port CSI0_PDWN
CSI0_RSET: R34.1 ; port CSI0_RSET
CSI0_SCLK: U1.86(GPIO56_PU/CSI0_SCLK/UART3_RXD) ; port CSI0_SCLK
EMMC_CLK: U1.77(GPIO73_PU/CSI1_D1/SD0_CLK/SPI2_DOUT/UART1_RTS) ; port EMMC_CLK
EMMC_CMD: U1.75(GPIO71_PU/CSI1_VSYNC/SD0_CMD/SPI2_SCLK/UART1_TXD) ; port EMMC_CMD
EMMC_D0/I2S0_BCLK: U1.81(GPIO77_PU/CSI1_D5/SD0_D0/RGB_D20/I2S0_BCLK) ; port EMMC_D0/I2S0_BCLK
EMMC_D1/I2S0_LRCLK: U1.80(GPIO76_PU/CSI1_D4/SD0_D1/RGB_D21/I2S0_LRCLK) ; port EMMC_D1/I2S0_LRCLK
EMMC_D2: U1.72(GPIO68_PU/CSI1_SCLK/SD0_D2/SPI2_CS0) ; port EMMC_D2
EMMC_D3: U1.73(GPIO69_PU/CSI1_PCLK/SD0_D3/SPI2_HOLD) ; port EMMC_D3
EMMC_D4: U1.74(GPIO70_PU/CSI1_HSYNC/SD0_D4/SPI2_DIN/UART1_RXD) ; port EMMC_D4
EMMC_D5: U1.76(GPIO72_PU/CSI1_D0/SD0_D5/SPI2_WP/UART1_CTS) ; port EMMC_D5
EMMC_D6: U1.78(GPIO74_PU/CSI1_D2/SD0_D6/RGB_D23/SPI2_CS1) ; port EMMC_D6
EMMC_D7/I2S0_DIN: U1.79(GPIO75_PU/CSI1_D3/SD0_D7/RGB_D22/I2S0_DIN) ; port EMMC_D7/I2S0_DIN
GPIO32: R18.2 U1.71(GPIO32_PU/I2C1_SCL)
GPIO83: R33.2 R34.2 U1.59(GPIO83_PU/I2C2_SCL/SPI2_CS0/UART2_RXD/I2S1_LRCLK)
GPIO84: R35.2 R36.2 U1.60(GPIO84_PU/I2C2_SDA/SPI2_SCLK/UART2_TXD/I2S1_BCLK)
GPIO85: R21.2 R22.2 U1.61(GPIO85_PU/I2C3_SCL/SPI2_DIN/UART3_RXD/I2S1_MCLK)
GPIO86: R23.2 R24.2 U1.62(GPIO86_PU/I2C3_SDA/SPI2_DOUT/UART3_TXD/I2S1_DIN)
I2S0_DOUT: U1.83(GPIO79_PU/CSI1_D7/I2C2_SDA/RGB_D18/I2S0_DOUT) ; port I2S0_DOUT
I2S0_MCLK: U1.82(GPIO78_PU/CSI1_D6/I2C2_SCL/RGB_D19/I2S0_MCLK) ; port I2S0_MCLK
RMII0_50MCLK: R9.2 ; port RMII0_50MCLK
RMII0_MDC: U1.37(GPIO1_PD/RMII0_MDC/SD2_D0/I2S0_LRCLK/I2C0_SDA) ; port RMII0_MDC
RMII0_MDIO: U1.36(GPIO0_PU/RMII0_MDIO/SD2_D1/I2S0_DIN/I2C0_SCL) ; port RMII0_MDIO
RMII0_RST: R21.1 ; port RMII0_RST
RMII0_RXD0: U1.40(GPIO4_PD/RMII0_RXD0/SD2_D3/I2S0_DOUT) ; port RMII0_RXD0
RMII0_RXD1: U1.41(GPIO5_PD/RMII0_RXD1/SD2_D2/PWM3) ; port RMII0_RXD1
RMII0_RXDV: U1.39(GPIO3_PD/RMII0_RXDV/SD2_CMD/I2S0_MCLK/PWM4) ; port RMII0_RXDV
RMII0_RXER: U1.38(GPIO2_PD/RMII0_RXER/SD2_CLK/I2S0_BCLK/PWM5) ; port RMII0_RXER
RMII0_TXD0: U1.43(GPIO7_PD/RMII0_TXD0/I2C3_SDA/PWM1/I2S1_BCLK) ; port RMII0_TXD0
RMII0_TXD1: U1.44(GPIO8_PD/RMII0_TXD1/UART3_RXD/PDM_CLK/I2S1_MCLK) ; port RMII0_TXD1
RMII0_TXEN: U1.45(GPIO9_PD/RMII0_TXEN/UART3_TXD/PDM_DATA/I2S1_DIN) ; port RMII0_TXEN
RMII1_50MCLK/CSI0_D4: R15.2 U1.94(GPIO64_PU/CSI0_D4/OPCLK1/I2C2_SCL/I2S1_LRCLK)
RMII1_MDC/CSI0_VSYNC/SD2_D0: U1.89(GPIO59_PU/CSI0_VSYNC/RMII1_MDC/SD2_D0) ; port RMII1_MDC/CSI0_VSYNC/SD2_D0
RMII1_MDIO/CSI0_HSYNC/SD2_D1: U1.88(GPIO58_PU/CSI0_HSYNC/RMII1_MDIO/SD2_D1) ; port RMII1_MDIO/CSI0_HSYNC/SD2_D1
RMII1_RST: R23.1 ; port RMII1_RST
RMII1_RXD0/CSI0_D2/SD2_D3: U1.92(GPIO62_PU/CSI0_D2/RMII1_RXD0/SD2_D3) ; port RMII1_RXD0/CSI0_D2/SD2_D3
RMII1_RXD1/CSI0_D3/SD2_D2: U1.93(GPIO63_PU/CSI0_D3/RMII1_RXD1/SD2_D2) ; port RMII1_RXD1/CSI0_D3/SD2_D2
RMII1_RXDV/CSI0_D1/SD2_CMD: U1.91(GPIO61_PU/CSI0_D1/RMII1_RXDV/SD2_CMD) ; port RMII1_RXDV/CSI0_D1/SD2_CMD
RMII1_RXER/CSI0_D0/SD2_CLK: U1.90(GPIO60_PU/CSI0_D0/RMII1_RXER/SD2_CLK) ; port RMII1_RXER/CSI0_D0/SD2_CLK
RMII1_TXD0/CSI0_D5: U1.95(GPIO65_PU/CSI0_D5/RMI1_TXD0/I2C2_SDA/I2S1_BCLK) ; port RMII1_TXD0/CSI0_D5
RMII1_TXD1/CSI0_D6: U1.96(GPIO66_PU/CSI0_D6/RMII1_TXD1/PDM_CLK/I2S1_MCLK) ; port RMII1_TXD1/CSI0_D6
RMII1_TXEN/CSI0_D7: U1.97(GPIO67_PU/CSI0_D7/RMII1_TXEN/PDM_DATA/I2S1_DIN) ; port RMII1_TXEN/CSI0_D7
SPI0_CS0: R30.2 R31.2 U1.126(GPIO10_PU/SPI0_CS0)
SPI0_CS1: R29.2 R32.2 U1.1(GPIO82_PU/PWM0/SPI0_CS1/SPI1_CS1)
SPI0_DIN: U1.125(GPIO12_PU/SPI0_DIN) U2.2(SO) U3.2(SO)
SPI0_DOUT: R4.2 U1.124(GPIO15_PU/SPI0_DOUT) U2.5(SI) U3.5(SI)
SPI0_HOLD: R3.2 U1.128(GPIO11_PU/SPI0_HOLD) U2.7(HOLD#) U3.7(#HOLD)
SPI0_SCLK: U1.127(GPIO13_PU/SPI0_SCLK) U2.6(SCK) U3.6(CLK)
SPI0_WP: R1.2 U1.123(GPIO14_PU/SPI0_WP) U2.3(WP#) U3.3(#WP)
TF_CLK: R17.2 U1.55(GPIO18_PD/SPI1_SCLK/SD1_CLK) ; port TF_CLK
TF_CMD: U1.56(GPIO19_PU/SPI1_DOUT/SD1_CMD) ; port TF_CMD
TF_D0: U1.54(GPIO17_PU/SPI1_DIN/SD1_D0/I2C1_SDA/PWM4) ; port TF_D0
TF_D1: U1.53(GPIO16_PU/SPI1_CS0/SD1_D1/I2C1_SCL/PWM1) ; port TF_D1
TF_D2: U1.58(GPIO21_PU/SPI1_HOLD/SD1_D2/UART2_TXD/PWM2) ; port TF_D2
TF_D3: U1.57(GPIO20_PU/SPI1_WP/SD1_D3/UART2_RXD/PWM3) ; port TF_D3
TF_DET: R17.1 R18.1 ; port TF_DET
UART0_RXD: U1.47(GPIO22_PU/UART0_RXD/PWM4) ; port UART0_RXD
UART0_TXD: U1.46(GPIO23_PU/UART0_TXD/PWM5) ; port UART0_TXD
UART2_RXD: R33.1 ; port UART2_RXD
UART2_TXD: R35.1 ; port UART2_TXD
UART3_RXD: R22.1 ; port UART3_RXD
UART3_TXD: R24.1 ; port UART3_TXD
NetCON1_39: R4.1 ; port RE_BOOT
NetCON2_47: R15.1 ; port RMII1_50MCLK/CSI0_D4
NetR2_2: R2.2 R29.1 R30.1 U2.1(CE#)
NetR9_1: R9.1 U1.42(GPIO6_PU/OPCLK0/I2C3_SCL/PWM2/I2S1_LRCLK)
NetR19_2: R19.2 R31.1 R32.1 U3.1(#CE)

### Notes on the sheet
- (near U1) 注意！！！
  相关注意事项请查看硬件设计指南Ethernet接口
- 注意！！！
  默认启动为SPI0_CS0

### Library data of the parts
C1 C70 = CC0301040XX: C/C,100nF,25V,+/-5%,0603; Catalog: 陶瓷电容
C2 = CC0304751XX: C/C,4.7uF,16V,+/-10%,0603; Catalog: 陶瓷电容
C72 = CC0201040XX: C/C,100nF,25V,+/-5%,0402; Catalog: 陶瓷电容
FB1 = BE0306011XX: as FB6 on sheet AK376xE_POWER
R1-R3 R19 = CR0304720XX: Res,4.7K,1/10W,+/-5%,0603; Catalog: 贴片电阻
R4 = CR0301010XX: Res,100R,1/10W,+/-5%,0603; Catalog: 贴片电阻
R9 R15 = CR0333R00XX: Res,33R,1/10W,+/-1%,0603; Catalog: 贴片电阻
R17 = CR0301020XX: Res,1K,1/10W,+/-5%,0603; Remark: NC; Catalog: 贴片电阻
R18 R21 R23 R30 R32 R33 R35 = CR0300000XX: Res,0R,1/10W,+/-5%,0603; Catalog: 贴片电阻
R22 R24 R29 R31 R34 R36 = CR0300000XX: Res,0R,1/10W,+/-5%,0603; Remark: NC; Catalog: 贴片电阻
U1 = 11111111110: as U1 on sheet AK376xE_POWER
U2 = JCSOPAP03XX: IC：NOR Flash, Glga Device, GD25Q64ESIG, SOP8, 8MB, 3.3V; PCB DECAL: GDQ64BSIG_SOP8_1MM27_5X8MM; Catalog: 集成电路
U3 = JCDFNMC19XX: SPI-NAND FLASH,GigaDevice,GD5F1GQ5UEYIG,1Gbit SLC NAND Flash,2.7~3.6V,WSON8.; Source_Path: H:\SNOWBIRD-S\PLATFORM\SBS_LIB.OLB; PCB DECAL: GD5F1GQ4UAYIG_SOP8_1MM27_6X8MM; Catalog: 集成电路

## Sheet AK376xE_MIC.SchDoc: EVB_CBDM_AK376xE_V1.0.3
size A4; Revision: V1.0.3; SheetNumber: 6; SheetTotal: 7
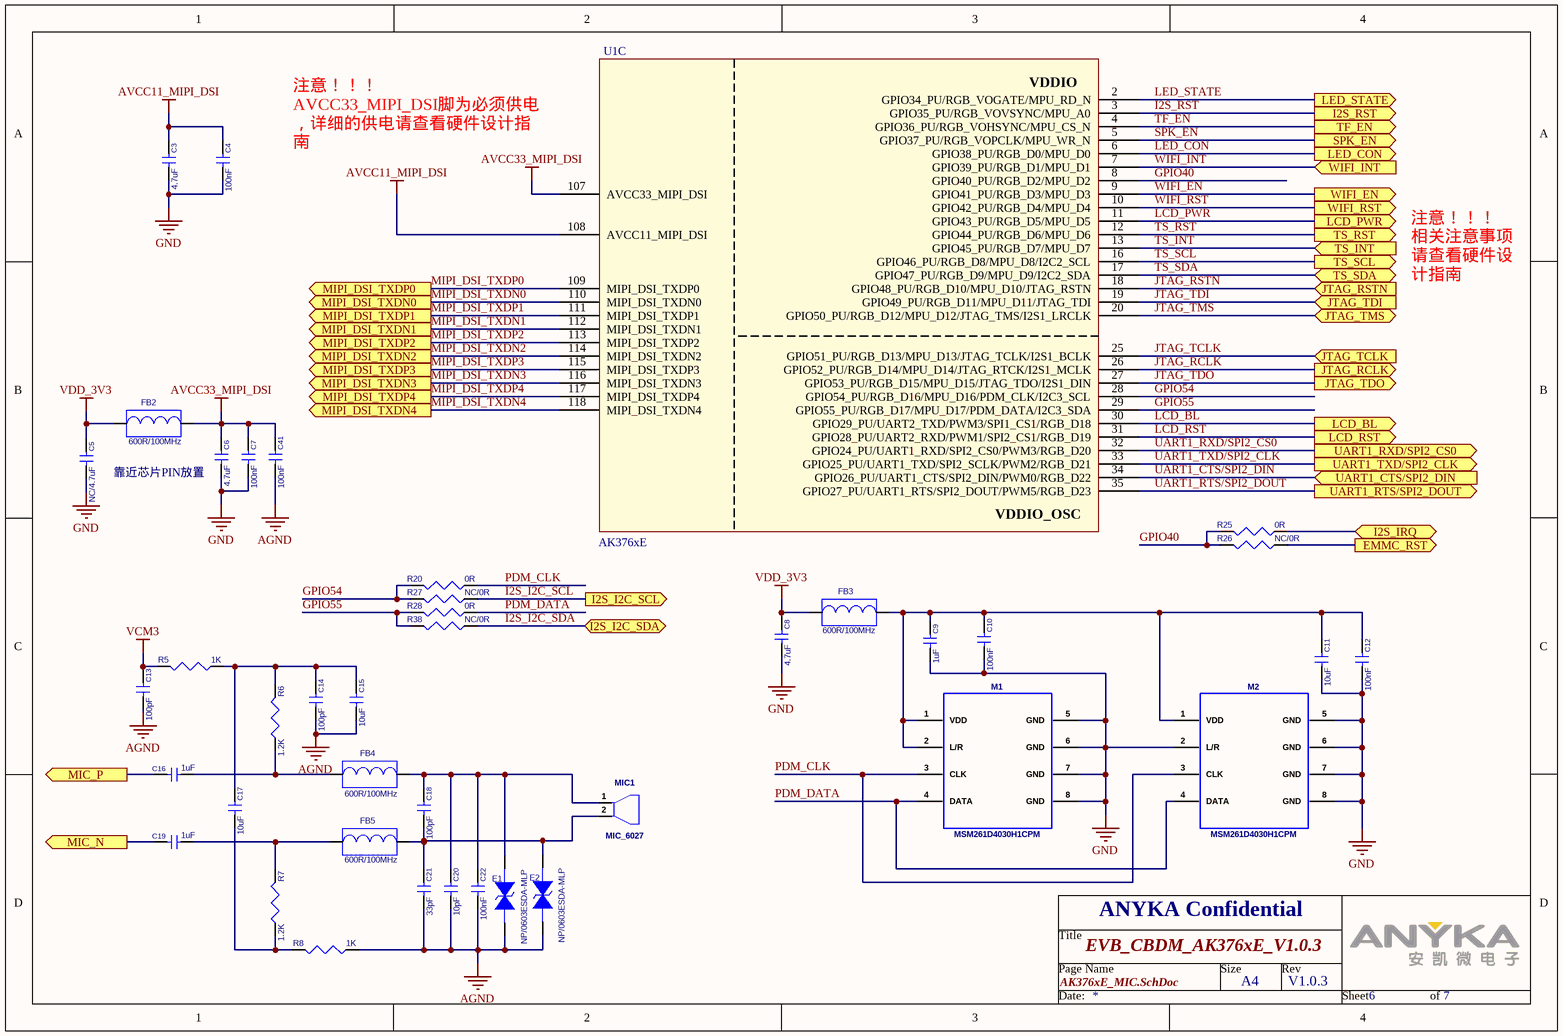
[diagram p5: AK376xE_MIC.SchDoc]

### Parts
C3  4.7uF  [C0402]
C4  100nF  [C0402]
C5  NC/4.7uF  [C0402]
C6  4.7uF  [C0402]
C7  100nF  [C0402]
C8  4.7uF  [C0603]
C9  1uF  [C0603]
C10  100nF  [C0603]
C11  10uF  [C0603]
C12  100nF  [C0603]
C13  100pF  [C0603]
C14  100pF  [C0603]
C15  10uF  [C0603]
C16  1uF  [C0603]
C17  10uF  [C0603]
C18  100pF  [C0603]
C19  1uF  [C0603]
C20  10pF  [C0603]
C21  33pF  [C0603]
C22  100nF  [C0603]
C41  100nF  [C0402]
E1  value NP/0603ESDA-MLP  [ESD0603]  (hidden comment: ESD0603)
E2  value NP/0603ESDA-MLP  [ESD0603]  (hidden comment: ESD0603)
FB2  600R/100MHz  [FB0603]
FB3  600R/100MHz  [FB0603]
FB4  600R/100MHz  [FB0603]
FB5  600R/100MHz  [FB0603]
M1  MSM261D4030H1CPM  [MSM261D4030H1]
M2  MSM261D4030H1CPM  [MSM261D4030H1]
MIC1  MIC_6027  [MIC_4MM_DIP]
R5  1K  [R0603]
R6  1.2K  [R0603]
R7  1.2K  [R0603]
R8  1K  [R0603]
R20  0R  [R0603]
R25  0R  [R0603]
R26  NC/0R  [R0603]
R27  NC/0R  [R0603]
R28  0R  [R0603]
R38  NC/0R  [R0603]
U1  AK376xE  [LQFP128_0MM4_16X16MM]  (part C of 3)

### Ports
EMMC_RST (out), I2S_I2C_SCL (out), I2S_I2C_SDA (bidir), I2S_IRQ (bidir), I2S_RST (out), JTAG_RCLK (out), JTAG_RSTN (in), JTAG_TCLK (in), JTAG_TDI (in), JTAG_TDO (out), JTAG_TMS (bidir), LCD_BL (out), LCD_PWR (out), LCD_RST (out), LED_CON (out), LED_STATE (out), MIC_N (out), MIC_P (out), MIPI_DSI_TXDN0 (out), MIPI_DSI_TXDN1 (out), MIPI_DSI_TXDN2 (out), MIPI_DSI_TXDN3 (out), MIPI_DSI_TXDN4 (out), MIPI_DSI_TXDP0 (out), MIPI_DSI_TXDP1 (out), MIPI_DSI_TXDP2 (out), MIPI_DSI_TXDP3 (out), MIPI_DSI_TXDP4 (out), SPK_EN (out), TF_EN (out), TS_INT (in), TS_RST (out), TS_SCL (out), TS_SDA (bidir), UART1_CTS/SPI2_DIN (in), UART1_RTS/SPI2_DOUT (out), UART1_RXD/SPI2_CS0 (out), UART1_TXD/SPI2_CLK (out), WIFI_EN (out), WIFI_INT (in), WIFI_RST (out)

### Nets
AGND: C13.2 C14.2 C15.2 C20.2 C21.2 C22.2 C41.2 E1.2 E2.2 R8.1
AVCC11_MIPI_DSI: C3.1 C4.1 U1.108(AVCC11_MIPI_DSI)
AVCC33_MIPI_DSI: C6.1 C7.1 C41.1 FB2.2 U1.107(AVCC33_MIPI_DSI)
GND: C3.2 C4.2 C5.2 C6.2 C7.2 C8.2 C9.2 C10.2 C11.2 C12.2 M1.5(GND) M1.6(GND) M1.7(GND) M1.8(GND) M2.2(L/R) M2.5(GND) M2.6(GND) M2.7(GND) M2.8(GND)
VCM3: C13.1 R5.2
VDD_3V3: C5.1 C8.1 FB2.1 FB3.1
GPIO40: R25.2 R26.2 U1.8(GPIO40_PU/RGB_D2/MPU_D2)
GPIO54: R20.2 R27.2 U1.28(GPIO54_PU/RGB_D16/MPU_D16/PDM_CLK/I2C3_SCL)
GPIO55: R28.2 R38.2 U1.29(GPIO55_PU/RGB_D17/MPU_D17/PDM_DATA/I2C3_SDA)
I2S_I2C_SCL: R27.1 ; port I2S_I2C_SCL
I2S_I2C_SDA: R38.1 ; port I2S_I2C_SDA
I2S_RST: U1.3(GPIO35_PU/RGB_VOVSYNC/MPU_A0) ; port I2S_RST
JTAG_RCLK: U1.26(GPIO52_PU/RGB_D14/MPU_D14/JTAG_RTCK/I2S1_MCLK) ; port JTAG_RCLK
JTAG_RSTN: U1.18(GPIO48_PU/RGB_D10/MPU_D10/JTAG_RSTN) ; port JTAG_RSTN
JTAG_TCLK: U1.25(GPIO51_PU/RGB_D13/MPU_D13/JTAG_TCLK/I2S1_BCLK) ; port JTAG_TCLK
JTAG_TDI: U1.19(GPIO49_PU/RGB_D11/MPU_D11/JTAG_TDI) ; port JTAG_TDI
JTAG_TDO: U1.27(GPIO53_PU/RGB_D15/MPU_D15/JTAG_TDO/I2S1_DIN) ; port JTAG_TDO
JTAG_TMS: U1.20(GPIO50_PU/RGB_D12/MPU_D12/JTAG_TMS/I2S1_LRCLK) ; port JTAG_TMS
LCD_BL: U1.30(GPIO29_PU/UART2_TXD/PWM3/SPI1_CS1/RGB_D18) ; port LCD_BL
LCD_PWR: U1.11(GPIO43_PU/RGB_D5/MPU_D5) ; port LCD_PWR
LCD_RST: U1.31(GPIO28_PU/UART2_RXD/PWM1/SPI2_CS1/RGB_D19) ; port LCD_RST
LED_CON: U1.6(GPIO38_PU/RGB_D0/MPU_D0) ; port LED_CON
LED_STATE: U1.2(GPIO34_PU/RGB_VOGATE/MPU_RD_N) ; port LED_STATE
MIC_N: C19.1 ; port MIC_N
MIC_P: C16.1 ; port MIC_P
MIPI_DSI_TXDN0: U1.110(MIPI_DSI_TXDN0) ; port MIPI_DSI_TXDN0
MIPI_DSI_TXDN1: U1.112(MIPI_DSI_TXDN1) ; port MIPI_DSI_TXDN1
MIPI_DSI_TXDN2: U1.114(MIPI_DSI_TXDN2) ; port MIPI_DSI_TXDN2
MIPI_DSI_TXDN3: U1.116(MIPI_DSI_TXDN3) ; port MIPI_DSI_TXDN3
MIPI_DSI_TXDN4: U1.118(MIPI_DSI_TXDN4) ; port MIPI_DSI_TXDN4
MIPI_DSI_TXDP0: U1.109(MIPI_DSI_TXDP0) ; port MIPI_DSI_TXDP0
MIPI_DSI_TXDP1: U1.111(MIPI_DSI_TXDP1) ; port MIPI_DSI_TXDP1
MIPI_DSI_TXDP2: U1.113(MIPI_DSI_TXDP2) ; port MIPI_DSI_TXDP2
MIPI_DSI_TXDP3: U1.115(MIPI_DSI_TXDP3) ; port MIPI_DSI_TXDP3
MIPI_DSI_TXDP4: U1.117(MIPI_DSI_TXDP4) ; port MIPI_DSI_TXDP4
PDM_CLK: M1.3(CLK) M2.3(CLK) R20.1
PDM_DATA: M1.4(DATA) M2.4(DATA) R28.1
SPK_EN: U1.5(GPIO37_PU/RGB_VOPCLK/MPU_WR_N) ; port SPK_EN
TF_EN: U1.4(GPIO36_PU/RGB_VOHSYNC/MPU_CS_N) ; port TF_EN
TS_INT: U1.13(GPIO45_PU/RGB_D7/MPU_D7) ; port TS_INT
TS_RST: U1.12(GPIO44_PU/RGB_D6/MPU_D6) ; port TS_RST
TS_SCL: U1.16(GPIO46_PU/RGB_D8/MPU_D8/I2C2_SCL) ; port TS_SCL
TS_SDA: U1.17(GPIO47_PU/RGB_D9/MPU_D9/I2C2_SDA) ; port TS_SDA
UART1_CTS/SPI2_DIN: U1.34(GPIO26_PU/UART1_CTS/SPI2_DIN/PWM0/RGB_D22) ; port UART1_CTS/SPI2_DIN
UART1_RTS/SPI2_DOUT: U1.35(GPIO27_PU/UART1_RTS/SPI2_DOUT/PWM5/RGB_D23) ; port UART1_RTS/SPI2_DOUT
UART1_RXD/SPI2_CS0: U1.32(GPIO24_PU/UART1_RXD/SPI2_CS0/PWM3/RGB_D20) ; port UART1_RXD/SPI2_CS0
UART1_TXD/SPI2_CLK: U1.33(GPIO25_PU/UART1_TXD/SPI2_SCLK/PWM2/RGB_D21) ; port UART1_TXD/SPI2_CLK
WIFI_EN: U1.9(GPIO41_PU/RGB_D3/MPU_D3) ; port WIFI_EN
WIFI_INT: U1.7(GPIO39_PU/RGB_D1/MPU_D1) ; port WIFI_INT
WIFI_RST: U1.10(GPIO42_PU/RGB_D4/MPU_D4) ; port WIFI_RST
NetC9_1: C9.1 C10.1 C11.1 C12.1 FB3.2 M1.1(VDD) M1.2(L/R) M2.1(VDD)
NetC14_1: C14.1 C15.1 C17.1 R5.1 R6.2
NetC16_2: C16.2 FB4.1 R6.1
NetC17_2: C17.2 R7.1 R8.2
NetC18_1: C18.1 C20.1 C22.1 E1.1 FB4.2 MIC1.1
NetC18_2: C18.2 C21.1 E2.1 FB5.2 MIC1.2
NetC19_2: C19.2 FB5.1 R7.2
NetCON3_35: R26.1 ; port EMMC_RST
NetCON3_48: R25.1 ; port I2S_IRQ

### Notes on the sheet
- 注意！！！
  AVCC33_MIPI_DSI脚为必须供电，详细的供电请查看硬件设计指南
- 注意！！！
  相关注意事项请查看硬件设计指南
- 靠近芯片PIN放置

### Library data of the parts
C3 C6 = CC0204751XX: C/C,4.7uF,10V,+/-10%,0402; Catalog: 陶瓷电容
C4 C7 C41 = CC0201040XX: C/C,100nF,25V,+/-5%,0402; Catalog: 陶瓷电容
C5 = CC0204751XX: C/C,4.7uF,10V,+/-10%,0402; Remark: NC; Catalog: 陶瓷电容
C8 = CC0304751XX: C/C,4.7uF,16V,+/-10%,0603; Catalog: 陶瓷电容
C9 C16 C19 = CC0301055XX: C/C,1uF,16V,+/-10%,0603; Catalog: 陶瓷电容
C10 C12 C22 = CC0301040XX: C/C,100nF,25V,+/-5%,0603; Catalog: 陶瓷电容
C11 C15 C17 = CC0301061XX: C/C,10uF,25V,+/-20%,0603; Catalog: 陶瓷电容
C13 C14 C18 = CC0301010XX: C/C,100pF,25V,+/-5%,0603; Catalog: 陶瓷电容
C20 = CC0301000XX: C/C,10pF,25V,+/-5%,0603; Catalog: 陶瓷电容
C21 = CC0303300XX: C/C,33pF,25V,+/-5%,0603; Catalog: 陶瓷电容
E1 E2 = ED0314000XX: PESD1608H140CR15GPT,0603; ROOM: power; Source_Path: F:\PROJECTFILES\CADENCE\AK9802PLATFORM\AK98XX_MB_V0-0715.DSN; Remark: NC; Catalog: ESD Protectors
FB2-FB5 = BE0306011XX: as FB6 on sheet AK376xE_POWER
M1 M2 = MP4030941XX: MIC, PDM digital output, MSM261D4030H1CPM ,4mm×3mm×1mm; Catalog: Microphone
MIC1 = MP6015380XX: Pansonic MICROPHONE,∮6mm,H=2.7MM,38dB+/2dB,2pin直插件
R5 R8 = CR0301020XX: Res,1K,1/10W,+/-5%,0603; Catalog: 贴片电阻
R6 R7 = CR0312010XX: Res,1.2K,1/10W,+/-1%,0603; Catalog: 贴片电阻
R20 R25 R28 = CR0300000XX: Res,0R,1/10W,+/-5%,0603; Catalog: 贴片电阻
R26 R27 R38 = CR0300000XX: as R22 on sheet AK376xE_FLASH
U1 = 11111111110: as U1 on sheet AK376xE_POWER

## Sheet POWER.SchDoc: EVB_CBDM_AK376xE_V1.0.3
size A4; Revision: V1.0.3; SheetNumber: 7; SheetTotal: 7
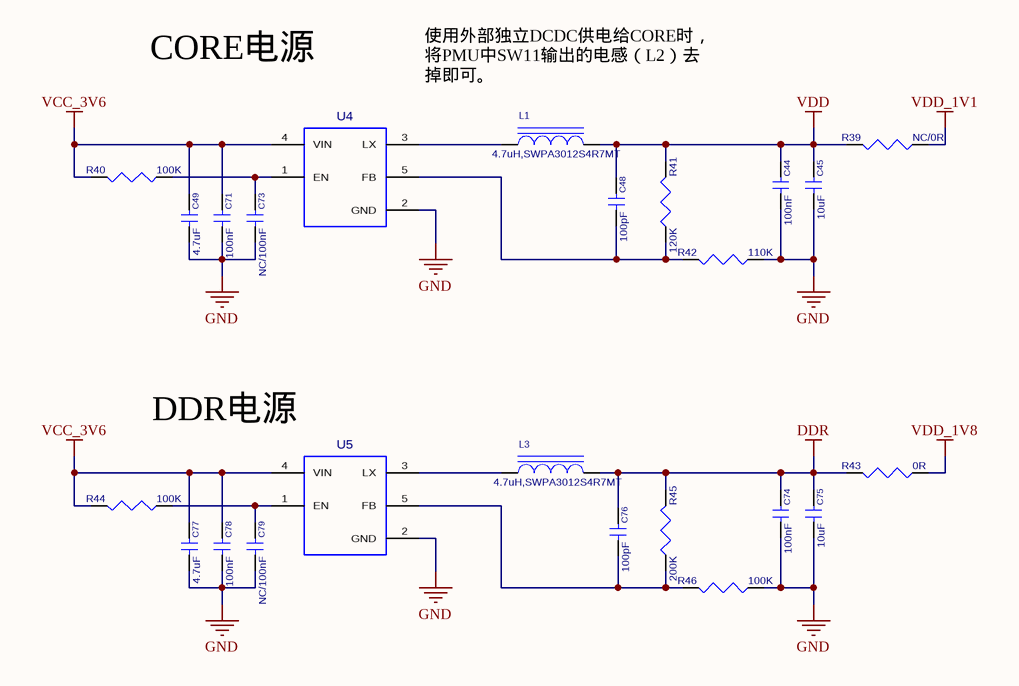
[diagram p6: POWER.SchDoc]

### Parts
C44  100nF  [C0402]
C45  10uF  [C0603]
C48  100pF  [C0402]
C49  4.7uF  [C0402]
C71  100nF  [C0402]
C73  NC/100nF  [C0402]
C74  100nF  [C0402]
C75  10uF  [C0603]
C76  100pF  [C0402]
C77  4.7uF  [C0402]
C78  100nF  [C0402]
C79  NC/100nF  [C0402]
L1  4.7uH,SWPA3012S4R7MT  [L_SWPA3012_3X3MM]
L3  4.7uH,SWPA3012S4R7MT  [L_SWPA3012_3X3MM]
R39  NC/0R  [R0805]
R40  100K  [R0402]
R41  120K  [R0402]
R42  110K  [R0402]
R43  0R  [R0805]
R44  100K  [R0402]
R45  200K  [R0402]
R46  100K  [R0402]
U4  PAM2312_SOT23_5  [PAM2312_SOT23_5]  (value not drawn)
U5  PAM2312_SOT23_5  [PAM2312_SOT23_5]  (value not drawn)

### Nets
DDR: C74.1 C75.1 C76.1 L3.2 R43.2 R45.2
GND: C44.2 C45.2 C49.2 C71.2 C73.2 C74.2 C75.2 C77.2 C78.2 C79.2 R42.1 R46.1 U4.2(GND) U5.2(GND)
VCC_3V6: C49.1 C71.1 C77.1 C78.1 R40.2 R44.2 U4.4(VIN) U5.4(VIN)
VDD: C44.1 C45.1 C48.1 L1.2 R39.2 R41.2
VDD_1V1: R39.1
VDD_1V8: R43.1
NetC48_2: C48.2 R41.1 R42.2 U4.5(FB)
NetC73_1: C73.1 R40.1 U4.1(EN)
NetC76_2: C76.2 R45.1 R46.2 U5.5(FB)
NetC79_1: C79.1 R44.1 U5.1(EN)
NetL1_1: L1.1 U4.3(LX)
NetL3_1: L3.1 U5.3(LX)

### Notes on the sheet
- CORE电源
- 使用外部独立DCDC供电给CORE时，将PMU中SW11输出的电感（L2）去掉即可。
- (near U5) DDR电源

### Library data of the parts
C44 C71 C74 C78 = CC0201040XX: C/C,100nF,25V,+/-5%,0402; Catalog: 陶瓷电容
C45 C75 = CC0301064XX: C/C,10uF,6.3V,+/-20%,0603; Catalog: 陶瓷电容
C48 C76 = CC0201010XX: C/C,100pF,25V,+/-5%,0402; Catalog: 陶瓷电容
C49 C77 = CC0204751XX: C/C,4.7uF,10V,+/-10%,0402; Catalog: 陶瓷电容
C73 C79 = CC0201040XX: as C30 on sheet AK376xE_POWER
L1 L3 = WL1C04R70XX: as L2 on sheet AK376xE_POWER
R39 = CR0500000XX: Res,0R,1/8W,+/-5%,0805; Remark: NC; Catalog: 贴片电阻
R40 R44 R46 = CR0210030XX: Res,100K,1/16W,+/-1%,0402; Catalog: 贴片电阻
R41 = CR0201240XX: Res,120K,1/16W,+/-1%,0402; Catalog: 贴片电阻
R42 = CR0201140XX: 贴片电阻 通用 res，110k，1/16W,+/-1%,0402；
R43 = CR0500000XX: Res,0R,1/8W,+/-5%,0805; Catalog: 贴片电阻
R45 = CR0220030XX: Res,200K,1/16W,+/-1%,0402; Catalog: 贴片电阻
U4 U5 = JCSXTPW60XX: PowerIC,PAM,PAM2312AABADJ,SOT23,5pin; Manufacturer #1: XICOR; Sim.Analog.Order: Model$; PCB DECAL: PAM2312_SOT23-5; Catalog: 集成电路

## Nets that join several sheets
AGND: INTERFACE_CORE (CON1.6), AK376xE_POWER (5 pins), AK376xE_MIC (10 pins)
GND: INTERFACE_CORE (32 pins), AK376xE_POWER (47 pins), AK376xE_FLASH (6 pins), AK376xE_MIC (19 pins), POWER (14 pins)
VCC_3V6: INTERFACE_CORE (CON2.2 CON2.4), POWER (8 pins)
VCC_RTC: INTERFACE_CORE (CON2.3 CON2.5), AK376xE_POWER (C51.1 C52.1 D1.K U1.65)
VCM3: AK376xE_POWER (C65.1 C66.1 U1.103), AK376xE_MIC (C13.1 R5.2)
VCM_RESET: INTERFACE_CORE (CON1.2), AK376xE_POWER (C50.1 U1.104)
VDD_1V1: AK376xE_POWER (7 pins), POWER (R39.1)
VDD_1V8: AK376xE_POWER (12 pins), POWER (R43.1)
VDD_3V3: INTERFACE_CORE (CON2.8 CON2.10), AK376xE_POWER (9 pins), AK376xE_FLASH (FB1.2), AK376xE_MIC (C5.1 C8.1 FB2.1 FB3.1)
VDDIO: AK376xE_POWER (5 pins), AK376xE_FLASH (U1.70)
VDDIO_CSI0: INTERFACE_CORE (CON2.6), AK376xE_FLASH (C72.1 U1.98)
AK_DM: INTERFACE_CORE (CON1.40), AK376xE_POWER (U1.121)
AK_DP: INTERFACE_CORE (CON1.38), AK376xE_POWER (U1.120)
CSI0_I2C_SCL: INTERFACE_CORE (CON2.36), AK376xE_FLASH (U1.85)
CSI0_I2C_SDA: INTERFACE_CORE (CON2.35), AK376xE_FLASH (U1.84)
CSI0_PCLK: INTERFACE_CORE (CON2.38), AK376xE_FLASH (U1.87)
CSI0_PDWN: INTERFACE_CORE (CON2.33), AK376xE_FLASH (R36.1)
CSI0_RSET: INTERFACE_CORE (CON2.34), AK376xE_FLASH (R34.1)
CSI0_SCLK: INTERFACE_CORE (CON2.37), AK376xE_FLASH (U1.86)
EMMC_CLK: INTERFACE_CORE (CON2.21), AK376xE_FLASH (U1.77)
EMMC_CMD: INTERFACE_CORE (CON2.18), AK376xE_FLASH (U1.75)
EMMC_D0/I2S0_BCLK: INTERFACE_CORE (CON2.24), AK376xE_FLASH (U1.81)
EMMC_D1/I2S0_LRCLK: INTERFACE_CORE (CON2.22), AK376xE_FLASH (U1.80)
EMMC_D2: INTERFACE_CORE (CON2.15), AK376xE_FLASH (U1.72)
EMMC_D3: INTERFACE_CORE (CON2.16), AK376xE_FLASH (U1.73)
EMMC_D4: INTERFACE_CORE (CON2.17), AK376xE_FLASH (U1.74)
EMMC_D5: INTERFACE_CORE (CON2.19), AK376xE_FLASH (U1.76)
EMMC_D6: INTERFACE_CORE (CON2.20), AK376xE_FLASH (U1.78)
EMMC_D7/I2S0_DIN: INTERFACE_CORE (CON2.23), AK376xE_FLASH (U1.79)
HPOUT: INTERFACE_CORE (CON1.4), AK376xE_POWER (U1.106)
I2S0_DOUT: INTERFACE_CORE (CON2.26), AK376xE_FLASH (U1.83)
I2S0_MCLK: INTERFACE_CORE (CON2.25), AK376xE_FLASH (U1.82)
I2S_I2C_SCL: INTERFACE_CORE (CON3.50), AK376xE_MIC (R27.1)
I2S_I2C_SDA: INTERFACE_CORE (CON3.49), AK376xE_MIC (R38.1)
I2S_RST: INTERFACE_CORE (CON3.47), AK376xE_MIC (U1.3)
JTAG_RCLK: INTERFACE_CORE (CON4.4), AK376xE_MIC (U1.26)
JTAG_RSTN: INTERFACE_CORE (CON4.2), AK376xE_MIC (U1.18)
JTAG_TCLK: INTERFACE_CORE (CON4.3), AK376xE_MIC (U1.25)
JTAG_TDI: INTERFACE_CORE (CON4.1), AK376xE_MIC (U1.19)
JTAG_TDO: INTERFACE_CORE (CON4.5), AK376xE_MIC (U1.27)
JTAG_TMS: INTERFACE_CORE (CON4.6), AK376xE_MIC (U1.20)
KEY_AIN0: INTERFACE_CORE (CON1.1), AK376xE_POWER (U1.100)
LCD_BL: INTERFACE_CORE (CON3.34), AK376xE_MIC (U1.30)
LCD_PWR: INTERFACE_CORE (CON3.40), AK376xE_MIC (U1.11)
LCD_RST: INTERFACE_CORE (CON3.33), AK376xE_MIC (U1.31)
LED_CON: INTERFACE_CORE (CON3.36), AK376xE_MIC (U1.6)
LED_STATE: INTERFACE_CORE (CON3.46), AK376xE_MIC (U1.2)
MIC_N: AK376xE_POWER (U1.102), AK376xE_MIC (C19.1)
MIC_P: AK376xE_POWER (U1.101), AK376xE_MIC (C16.1)
MIPI_DSI_TXDN0: INTERFACE_CORE (CON1.8), AK376xE_MIC (U1.110)
MIPI_DSI_TXDN1: INTERFACE_CORE (CON1.14), AK376xE_MIC (U1.112)
MIPI_DSI_TXDN2: INTERFACE_CORE (CON1.20), AK376xE_MIC (U1.114)
MIPI_DSI_TXDN3: INTERFACE_CORE (CON1.26), AK376xE_MIC (U1.116)
MIPI_DSI_TXDN4: INTERFACE_CORE (CON1.32), AK376xE_MIC (U1.118)
MIPI_DSI_TXDP0: INTERFACE_CORE (CON1.10), AK376xE_MIC (U1.109)
MIPI_DSI_TXDP1: INTERFACE_CORE (CON1.16), AK376xE_MIC (U1.111)
MIPI_DSI_TXDP2: INTERFACE_CORE (CON1.22), AK376xE_MIC (U1.113)
MIPI_DSI_TXDP3: INTERFACE_CORE (CON1.28), AK376xE_MIC (U1.115)
MIPI_DSI_TXDP4: INTERFACE_CORE (CON1.34), AK376xE_MIC (U1.117)
NetCON1_39: INTERFACE_CORE (CON1.39), AK376xE_FLASH (R4.1)
NetCON2_47: INTERFACE_CORE (CON2.47), AK376xE_FLASH (R15.1)
NetCON3_35: INTERFACE_CORE (CON3.35), AK376xE_MIC (R26.1)
NetCON3_48: INTERFACE_CORE (CON3.48), AK376xE_MIC (R25.1)
RMII0_50MCLK: INTERFACE_CORE (CON4.22), AK376xE_FLASH (R9.2)
RMII0_MDC: INTERFACE_CORE (CON4.15), AK376xE_FLASH (U1.37)
RMII0_MDIO: INTERFACE_CORE (CON4.14), AK376xE_FLASH (U1.36)
RMII0_RST: INTERFACE_CORE (CON2.11), AK376xE_FLASH (R21.1)
RMII0_RXD0: INTERFACE_CORE (CON4.18), AK376xE_FLASH (U1.40)
RMII0_RXD1: INTERFACE_CORE (CON4.19), AK376xE_FLASH (U1.41)
RMII0_RXDV: INTERFACE_CORE (CON4.17), AK376xE_FLASH (U1.39)
RMII0_RXER: INTERFACE_CORE (CON4.16), AK376xE_FLASH (U1.38)
RMII0_TXD0: INTERFACE_CORE (CON4.23), AK376xE_FLASH (U1.43)
RMII0_TXD1: INTERFACE_CORE (CON4.26), AK376xE_FLASH (U1.44)
RMII0_TXEN: INTERFACE_CORE (CON4.25), AK376xE_FLASH (U1.45)
RMII1_MDC/CSI0_VSYNC/SD2_D0: INTERFACE_CORE (CON2.40), AK376xE_FLASH (U1.89)
RMII1_MDIO/CSI0_HSYNC/SD2_D1: INTERFACE_CORE (CON2.39), AK376xE_FLASH (U1.88)
RMII1_RST: INTERFACE_CORE (CON2.12), AK376xE_FLASH (R23.1)
RMII1_RXD0/CSI0_D2/SD2_D3: INTERFACE_CORE (CON2.44), AK376xE_FLASH (U1.92)
RMII1_RXD1/CSI0_D3/SD2_D2: INTERFACE_CORE (CON2.46), AK376xE_FLASH (U1.93)
RMII1_RXDV/CSI0_D1/SD2_CMD: INTERFACE_CORE (CON2.43), AK376xE_FLASH (U1.91)
RMII1_RXER/CSI0_D0/SD2_CLK: INTERFACE_CORE (CON2.41), AK376xE_FLASH (U1.90)
RMII1_TXD0/CSI0_D5: INTERFACE_CORE (CON2.48), AK376xE_FLASH (U1.95)
RMII1_TXD1/CSI0_D6: INTERFACE_CORE (CON2.49), AK376xE_FLASH (U1.96)
RMII1_TXEN/CSI0_D7: INTERFACE_CORE (CON2.50), AK376xE_FLASH (U1.97)
SPK_EN: INTERFACE_CORE (CON3.45), AK376xE_MIC (U1.5)
TF_CLK: INTERFACE_CORE (CON4.34), AK376xE_FLASH (R17.2 U1.55)
TF_CMD: INTERFACE_CORE (CON4.33), AK376xE_FLASH (U1.56)
TF_D0: INTERFACE_CORE (CON4.29), AK376xE_FLASH (U1.54)
TF_D1: INTERFACE_CORE (CON4.30), AK376xE_FLASH (U1.53)
TF_D2: INTERFACE_CORE (CON4.35), AK376xE_FLASH (U1.58)
TF_D3: INTERFACE_CORE (CON4.36), AK376xE_FLASH (U1.57)
TF_DET: INTERFACE_CORE (CON3.37), AK376xE_FLASH (R17.1 R18.1)
TF_EN: INTERFACE_CORE (CON3.39), AK376xE_MIC (U1.4)
TS_INT: INTERFACE_CORE (CON2.32), AK376xE_MIC (U1.13)
TS_RST: INTERFACE_CORE (CON2.31), AK376xE_MIC (U1.12)
TS_SCL: INTERFACE_CORE (CON2.30), AK376xE_MIC (U1.16)
TS_SDA: INTERFACE_CORE (CON2.29), AK376xE_MIC (U1.17)
UART0_RXD: INTERFACE_CORE (CON4.27), AK376xE_FLASH (U1.47)
UART0_TXD: INTERFACE_CORE (CON4.28), AK376xE_FLASH (U1.46)
UART1_CTS/SPI2_DIN: INTERFACE_CORE (CON4.10), AK376xE_MIC (U1.34)
UART1_RTS/SPI2_DOUT: INTERFACE_CORE (CON4.9), AK376xE_MIC (U1.35)
UART1_RXD/SPI2_CS0: INTERFACE_CORE (CON4.8), AK376xE_MIC (U1.32)
UART1_TXD/SPI2_CLK: INTERFACE_CORE (CON4.7), AK376xE_MIC (U1.33)
UART2_RXD: INTERFACE_CORE (CON4.38), AK376xE_FLASH (R33.1)
UART2_TXD: INTERFACE_CORE (CON4.40), AK376xE_FLASH (R35.1)
UART3_RXD: INTERFACE_CORE (CON4.37), AK376xE_FLASH (R22.1)
UART3_TXD: INTERFACE_CORE (CON4.39), AK376xE_FLASH (R24.1)
WIFI_EN: INTERFACE_CORE (CON3.42), AK376xE_MIC (U1.9)
WIFI_INT: INTERFACE_CORE (CON3.41), AK376xE_MIC (U1.7)
WIFI_RST: INTERFACE_CORE (CON3.38), AK376xE_MIC (U1.10)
